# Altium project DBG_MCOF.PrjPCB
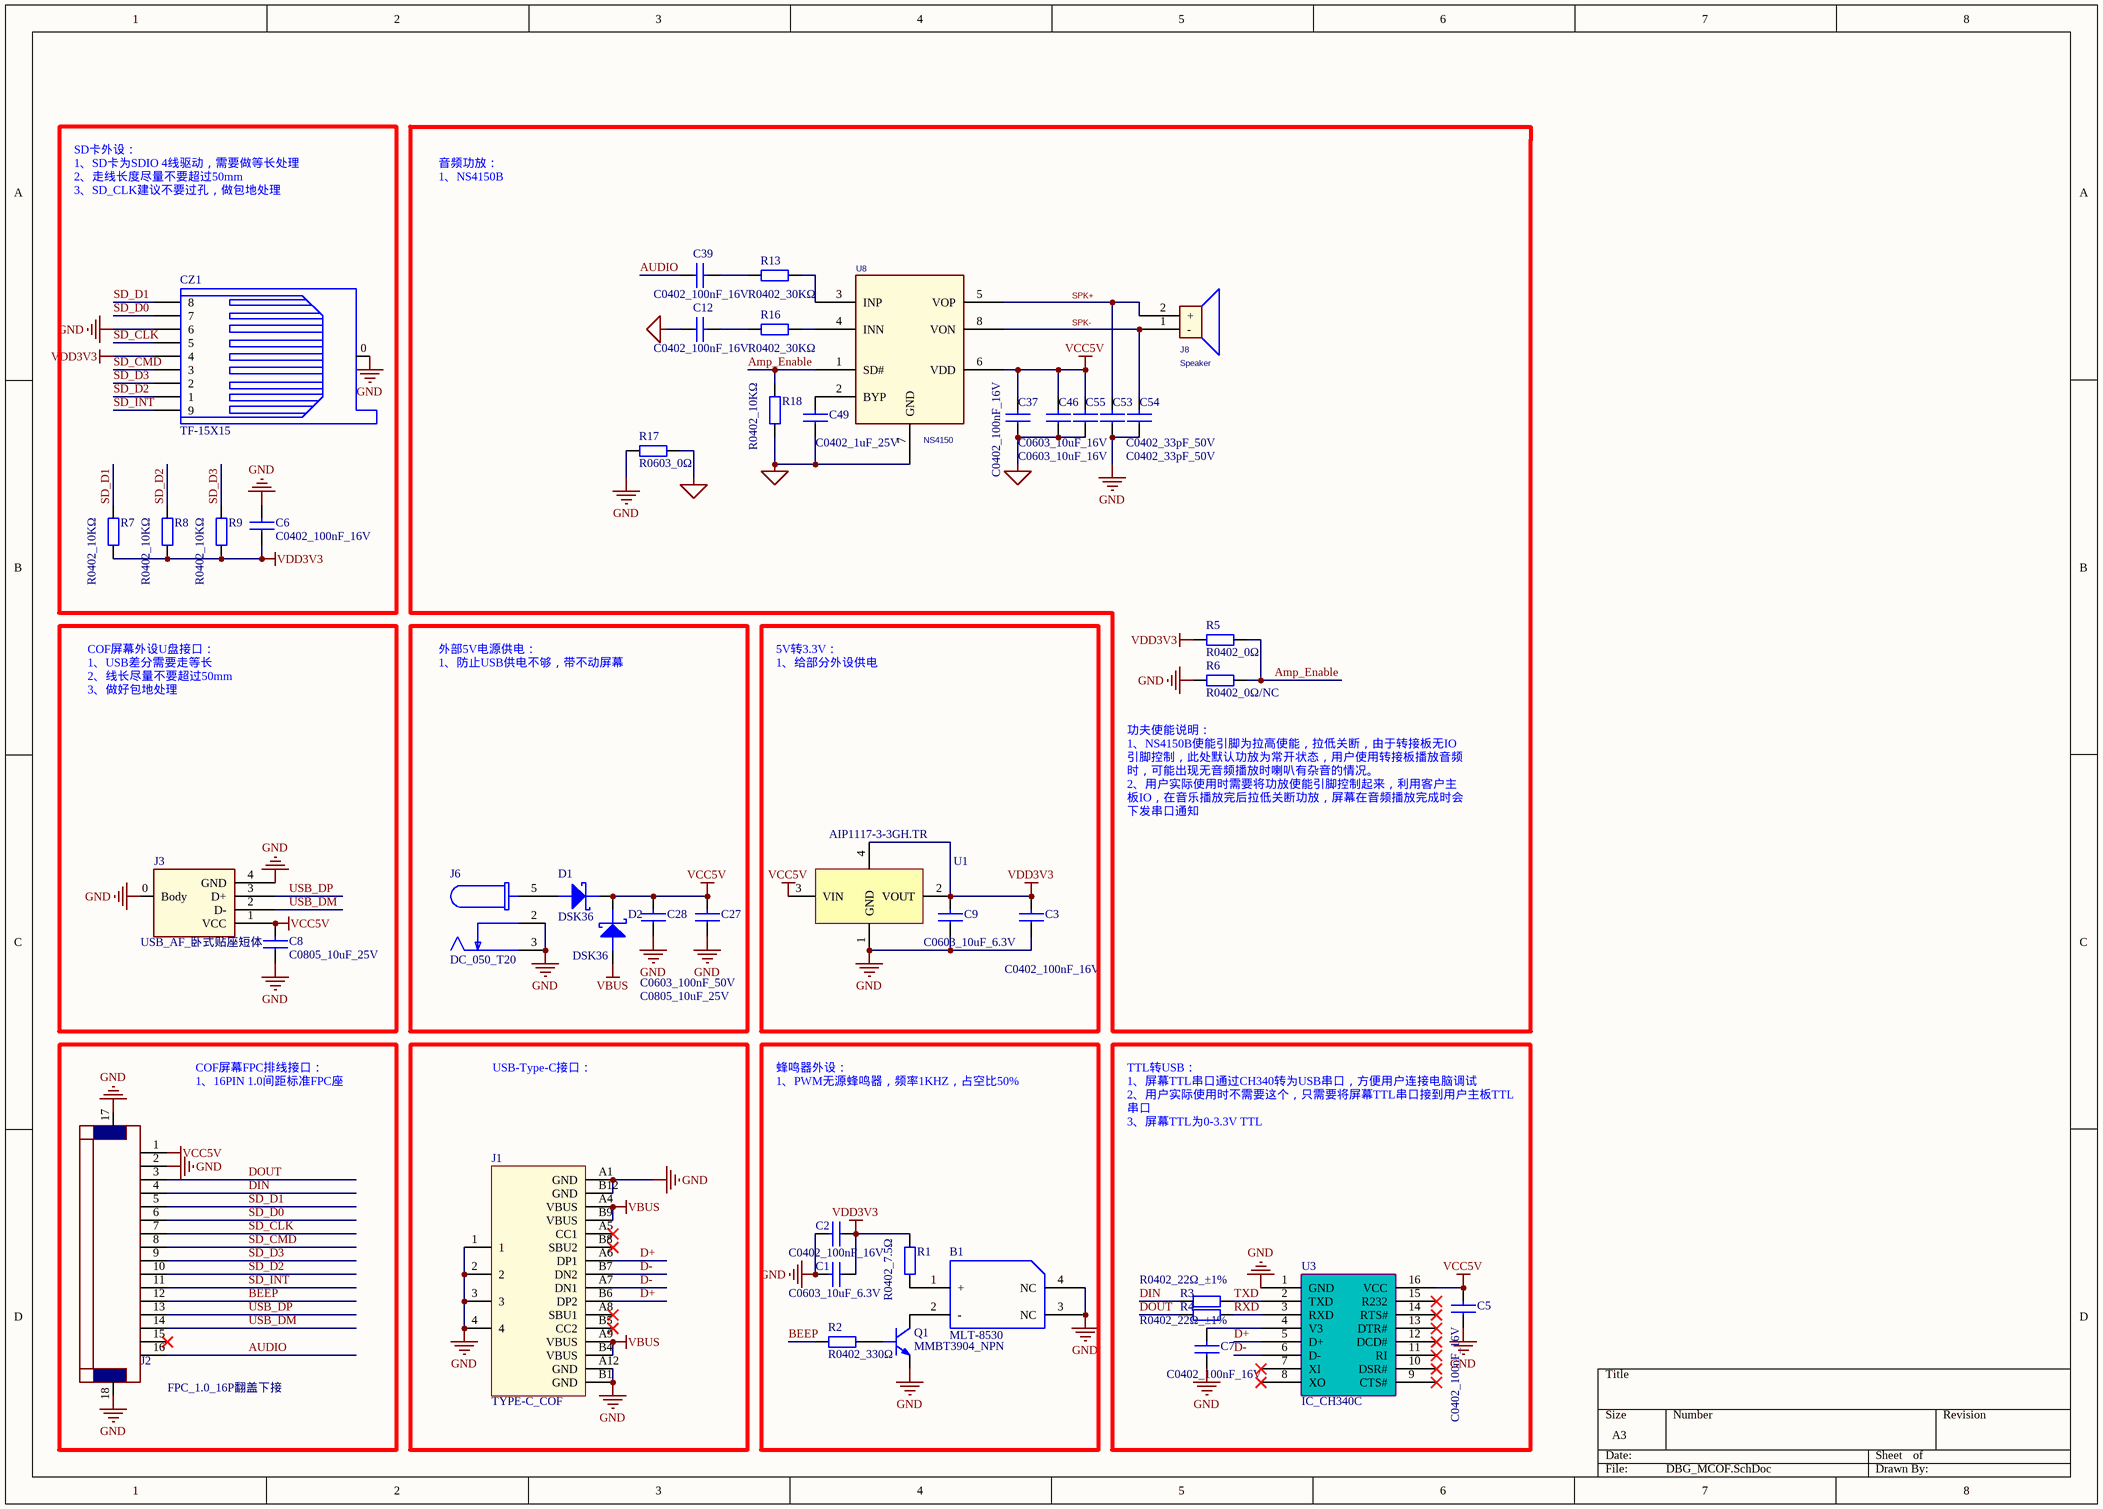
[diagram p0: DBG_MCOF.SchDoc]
2 sheets, 44 parts. Net scope: global (net labels, ports and power ports of the same name join across sheets).
Board file: DBG_MCOF.PcbDoc
Sheets:
  DBG_MCOF.SchDoc
  readme.SchDoc

## Sheet DBG_MCOF.SchDoc
size A3

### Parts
B1  MLT-8530  [BUZZER-SMD]
C1  C0603_10uF_6.3V  [0603C]
C2  C0402_100nF_16V  [0402C]
C3  C0402_100nF_16V  [0402C]
C5  C0402_100nF_16V  [0402C]
C6  C0402_100nF_16V  [0402C]
C7  C0402_100nF_16V  [0402C]
C8  C0805_10uF_25V  [0805C]
C9  C0603_10uF_6.3V  [0603C]
C12  C0402_100nF_16V  [0402C]
C27  C0603_100nF_50V  [0603C]
C28  C0805_10uF_25V  [0805C]
C37  C0402_100nF_16V  [0402C]
C39  C0402_100nF_16V  [0402C]
C46  C0603_10uF_16V  [0603C]
C49  C0402_1uF_25V  [0402C]
C53  C0402_33pF_50V  [0402C]
C54  C0402_33pF_50V  [0402C]
C55  C0603_10uF_16V  [0603C]
CZ1  TF-15X15  [T-F]
D1  DSK36  [SOD-123F]
D2  DSK36  [SOD-123F]
J1  TYPE-C_COF  [TYPE-C_COF]
J2  FPC_1.0_16P翻盖下接  [FFC-16S-1.0]
J3  USB_AF_卧式贴座短体  [USB-102SD]
J6  DC_050_T20  [DC_055_2.5]
J8  Speaker  [PH-2.0-2P]
Q1  MMBT3904_NPN  [SOT-23]
R1  R0402_7.5Ω  [0402R]
R2  R0402_330Ω  [0402R]
R3  R0402_22Ω_±1%  [0402R]
R4  R0402_22Ω_±1%  [0402R]
R5  R0402_0Ω  [0402R]
R6  R0402_0Ω/NC  [0402R]
R7  R0402_10KΩ  [0402R]
R8  R0402_10KΩ  [0402R]
R9  R0402_10KΩ  [0402R]
R13  R0402_30KΩ  [0402R]
R16  R0402_30KΩ  [0402R]
R17  R0603_0Ω  [0603R]
R18  R0402_10KΩ  [0402R]
U1  AIP1117-3-3GH.TR  [SOT89]
U3  IC_CH340C  [SOIC-16]
U8  NS4150  [MSOP-8]

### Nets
GND: B1.3(NC) B1.4(NC) C1.1 C2.1 C3.2 C5.2 C6.1 C7.2 C8.2 C9.2 C27.2 C28.2 C53.2 C54.2 CZ1.0 CZ1.6 J1.1 J1.2 J1.3 J1.4 J1.A1(GND) J1.A12(GND) J1.B1(GND) J1.B12(GND) J2.2 J2.17 J2.18 J3.0(Body) J3.4(GND) J6.2 J6.3 Q1.2(E) R6.2 R17.1 U1.1(GND) U3.1(GND)
GND_ADDA: C12.2 C37.2 C46.2 C49.2 C55.2 R17.2 R18.1 U8.7(GND)
VBUS: D2.1 J1.A4(VBUS) J1.A9(VBUS) J1.B4(VBUS) J1.B9(VBUS)
VCC5V: C5.1 C8.1 C27.1 C28.1 C37.1 C46.1 C55.1 D1.2 D2.2 J2.1 J3.1(VCC) U1.3(VIN) U3.16(VCC) U8.6(VDD)
VDD3V3: C1.2 C2.2 C3.1 C6.2 C9.1 CZ1.4 R1.2 R5.2 R7.1 R8.1 R9.1 U1.2(VOUT) U1.4
Amp_Enable: R5.1 R6.1 R18.2 U8.1(SD#)
AUDIO: C39.2 J2.16
BEEP: J2.12 R2.1
D+: J1.A6(DP1) J1.B6(DP2) U3.5(D+)
D-: J1.A7(DN1) J1.B7(DN2) U3.6(D-)
DIN: J2.4 R3.1
DOUT: J2.3 R4.1
RXD: R4.2 U3.3(RXD)
SD_CLK: CZ1.5 J2.7
SD_CMD: CZ1.3 J2.8
SD_D0: CZ1.7 J2.6
SD_D1: CZ1.8 J2.5 R7.2
SD_D2: CZ1.1 J2.10 R8.2
SD_D3: CZ1.2 J2.9 R9.2
SD_INT: CZ1.9 J2.11
SPK+: C53.1 J8.2(+) U8.5(VOP)
SPK-: C54.1 J8.1(-) U8.8(VON)
TXD: R3.2 U3.2(TXD)
USB_DM: J2.14 J3.2(D-)
USB_DP: J2.13 J3.3(D+)
NetB1_1: B1.1(+) R1.1
NetB1_2: B1.2(-) Q1.3(C)
NetC7_1: C7.1 U3.4(V3)
NetC12_1: C12.1 R16.1
NetC39_1: C39.1 R13.1
NetC49_1: C49.1 U8.2(BYP)
NetD1_1: D1.1 J6.5
NetQ1_1: Q1.1(B) R2.2
NetR13_2: R13.2 U8.3(INP)
NetR16_2: R16.2 U8.4(INN)

Not connected (* = marked no-connect by the designer): J1 A5(CC1)* A8(SBU1)* B5(CC2)* B8(SBU2)*; J2 15*; U3 7(XI)* 8(XO)* 9(CTS#)* 10(DSR#)* 11(RI)* 12(DCD#)* 13(DTR#)* 14(RTS#)* 15(R232)*

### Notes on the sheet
- SD卡外设：
  1、SD卡为SDIO 4线驱动，需要做等长处理
  2、走线长度尽量不要超过50mm
  3、SD_CLK建议不要过孔，做包地处理
- 音频功放：
  1、NS4150B
- COF屏幕外设U盘接口：
  1、USB差分需要走等长
  2、线长尽量不要超过50mm
  3、做好包地处理
- 外部5V电源供电：
  1、防止USB供电不够，带不动屏幕
- 5V转3.3V：
  1、给部分外设供电
- (near R6) 功夫使能说明：
  1、NS4150B使能引脚为拉高使能，拉低关断，由于转接板无IO
  引脚控制，此处默认功放为常开状态，用户使用转接板播放音频
  时，可能出现无音频播放时喇叭有杂音的情况。
  2、用户实际使用时需要将功放使能引脚控制起来，利用客户主
  板IO，在音乐播放完后拉低关断功放，屏幕在音频播放完成时会
  下发串口通知
- USB-Type-C接口：
- 蜂鸣器外设：
  1、PWM无源蜂鸣器，频率1KHZ，占空比50%
- COF屏幕FPC排线接口：
  1、16PIN 1.0间距标准FPC座
- TTL转USB：
  1、屏幕TTL串口通过CH340转为USB串口，方便用户连接电脑调试
  2、用户实际使用时不需要这个，只需要将屏幕TTL串口接到用户主板TTL串口
  3、屏幕TTL为0-3.3V TTL

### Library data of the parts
B1 = BUZZER_MLT-8530: 1.09.02.0001
C1 C9 = C0603_10uF_6.3V: 1.02.02.0030
C2 C3 C12 C37 C39 = C0402_100nF_16V: 1.02.01.0026
C5-C7 = C0402_100nF_16V: 1.19.01.0004
C8 = C0805_10uF_25V: 1.02.03.0017
C27 = C0603_100nF_50V: 1.02.01.0009
C28 = C0805_10uF_25V: 1.02.02.0009
C46 C55 = C0603_10uF_16V: 1.02.02.0029
C49 = C0402_1uF_25V: 1.02.01.0028
C53 C54 = C0402_33pF_50V: 1.02.01.0008
CZ1 = TF-15X15: 1.07.01.0027
D1 D2 = D_DSK36: 1.05.02.0014
J1 = TYPE-C_COF: 99
J2 = FPC_1.0_16P翻盖下接: 99
J3 = USB_AF_卧式贴座短体: 1.08.02.0008
J6 = DC_050_T20: 1.08.02.0088
J8 = SPEAKER_1
Q1 = Q_MMBT3904_NPN: 1.05.04.0004
R1 = R0402_7.5Ω: 1.01.01.0011
R2 = R0402_330Ω: 1.01.01.0022
R3 R4 = R0402_22Ω_±1%: 1.01.05.0002
R5 R6 = R0402_0Ω: 1.01.01.0001
R7-R9 R18 = R0402_10KΩ: 1.01.01.0045
R13 R16 = R0402_30KΩ: 1.01.01.0056
R17 = R0603_0Ω: 1.01.02.0001
U1 = IC_SPX1117M3-L-3-3/TR: 1.07.02.0004
U3 = IC_CH340G/340C
U8 = LPA2010

## Sheet readme.SchDoc
size A4
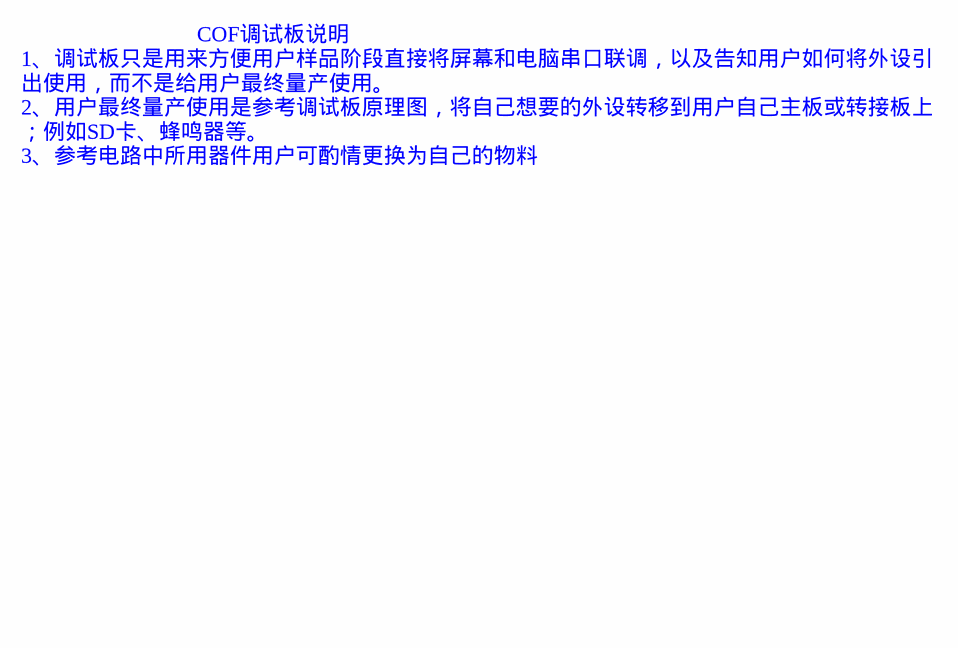
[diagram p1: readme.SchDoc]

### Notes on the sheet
- COF调试板说明
  1、调试板只是用来方便用户样品阶段直接将屏幕和电脑串口联调，以及告知用户如何将外设引出使用，而不是给用户最终量产使用。
  2、用户最终量产使用是参考调试板原理图，将自己想要的外设转移到用户自己主板或转接板上；例如SD卡、蜂鸣器等。
  3、参考电路中所用器件用户可酌情更换为自己的物料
